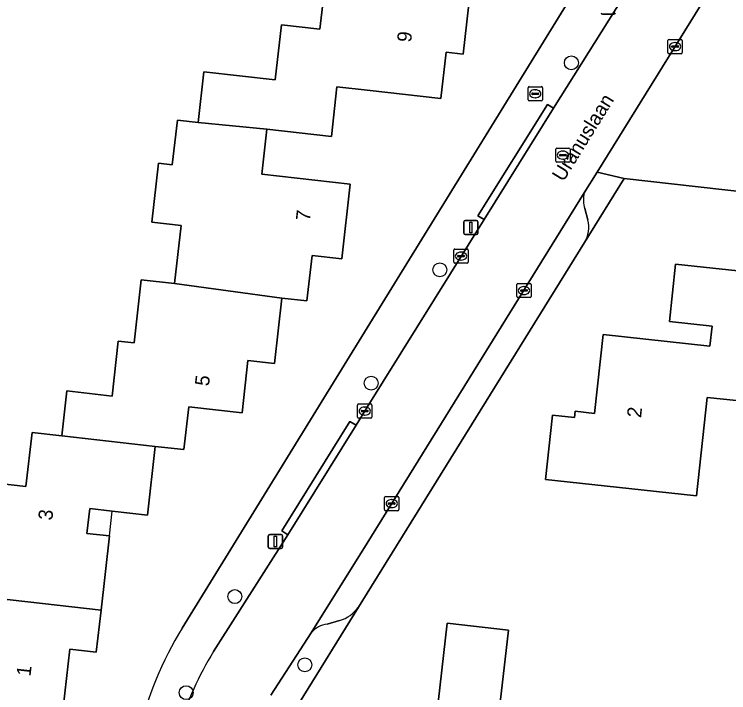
# Model space of a CAD drawing. Extents: x 162396 to 163643, y 386452 to 387406.
# Drawn here: x 162975.2 to 163025.4, y 386589 to 386636.7 of the extents above; entities that cross this region are included whole.
import ezdxf

# ---------------------------------------------------------------- set-up
doc = ezdxf.new("R2010")
doc.units = 0
for name, color, linetype in [('IMGEO_Boom', 7, 'Continuous'), ('IMGEO_Brandkraan', 7, 'Continuous'), ('IMGEO_Erf', 7, 'Continuous'), ('IMGEO_Kolk', 7, 'Continuous'), ('IMGEO_Lichtmast', 7, 'Continuous'), ('IMGEO_Openbare_ruimte_label', 7, 'Continuous'), ('IMGEO_Pand', 7, 'Continuous'), ('IMGEO_Pand_nummerreeks', 7, 'Continuous'), ('IMGEO_Pand_overbouw', 7, 'Continuous'), ('IMGEO_Parkeervlak_open', 7, 'Continuous'), ('IMGEO_Rijbaan_lokaal_open', 7, 'Continuous'), ('IMGEO_Rioolput', 7, 'Continuous'), ('IMGEO_Voetpad_open', 7, 'Continuous')]:
    doc.layers.add(name, color=color, linetype=linetype)

msp = doc.modelspace()

# ---------------------------------------------------------------- linework, layer by layer
at = {"layer": 'IMGEO_Boom'}
for centre in [(163014.332, 386633.247), (163005.108, 386618.72), (163000.288, 386610.754), (162990.719, 386595.774), (162995.628, 386590.981), (162987.307, 386589.03)]:
    msp.add_circle(centre, 0.489, dxfattribs=at)
at = {"layer": 'IMGEO_Brandkraan'}
for p, q in [((163011.297, 386630.65), (163011.297, 386631.502)), ((163011.372, 386631.576), (163012.224, 386631.576)), ((163011.599, 386631.119), (163011.997, 386631.119)), ((163011.785, 386631.356), (163011.81, 386631.356)), ((163012.298, 386631.502), (163012.298, 386630.65)), ((163011.556, 386631.07), (163011.556, 386631.082)), ((163011.994, 386631.033), (163011.596, 386631.033)), ((163011.808, 386630.796), (163011.783, 386630.796)), ((163012.04, 386631.082), (163012.04, 386631.07)), ((163012.224, 386630.576), (163011.372, 386630.576))]:
    msp.add_line(p, q, dxfattribs=at)
for points in [[(163011.297, 386630.65), (163011.297, 386631.502)], [(163011.372, 386631.576), (163012.224, 386631.576)], [(163012.298, 386631.502), (163012.298, 386630.65)], [(163012.224, 386630.576), (163011.372, 386630.576)]]:
    msp.add_lwpolyline(points, dxfattribs=at)
for centre, radius, start, end in [((163011.374, 386631.5), 0.0765, 91.552, 178.448), ((163011.374, 386631.5), 0.0765, 91.552, 178.448), ((163011.596, 386631.079), 0.0403, 85.8775, 175.7526), ((163012.001, 386631.081), 0.0386, 1.7309, 96.639), ((163012.222, 386631.5), 0.0765, 1.552, 88.448), ((163012.222, 386631.5), 0.0765, 1.552, 88.448), ((163011.374, 386630.652), 0.0765, 181.552, 268.448), ((163011.374, 386630.652), 0.0765, 181.552, 268.448), ((163011.593, 386631.069), 0.0366, 178.938, 274.7102), ((163011.997, 386631.076), 0.043, 264.8664, 352.4533), ((163012.222, 386630.652), 0.0765, 271.552, 358.448), ((163012.222, 386630.652), 0.0765, 271.552, 358.448)]:
    msp.add_arc(centre, radius, start, end, dxfattribs=at)
for centre, major_axis, ratio, start_param, end_param in [((163011.784, 386631.076), (-0.387, 0.002), 0.722429, 4.712389, 7.853982), ((163011.809, 386631.076), (-0.39, 0.002), 0.717154, 1.570796, 4.712389)]:
    msp.add_ellipse(centre, major_axis=major_axis, ratio=ratio, start_param=start_param, end_param=end_param, dxfattribs=at)
at = {"layer": 'IMGEO_Erf'}
for points in [[(163000, 386614.638), (163016.213, 386640.977)], [(162971.713, 386604.006), (162976.062, 386603.513), (162976.49, 386607.292), (162978.575, 386607.056), (162978.932, 386610.213), (162982.104, 386609.853), (162982.541, 386613.71), (162983.653, 386613.584), (162984.156, 386618.023), (162986.481, 386617.76), (162986.942, 386621.82), (162984.888, 386622.053), (162985.358, 386626.198), (162986.33, 386626.088), (162986.685, 386629.222), (162988.151, 386629.056), (162988.554, 386632.618), (162993.56, 386632.05), (162993.998, 386635.917), (162996.689, 386635.612), (162997.141, 386639.603)], [(163007.248, 386638.423), (163006.731, 386633.862), (163005.545, 386633.996), (163005.176, 386630.736), (163000, 386631.322), (162997.885, 386631.562), (162997.491, 386628.087), (162992.971, 386628.599), (162992.606, 386625.428), (162998.818, 386624.724), (162998.224, 386619.481), (162996.135, 386619.718), (162995.774, 386616.533), (162994.015, 386616.732), (162993.493, 386612.131), (162991.642, 386612.341), (162991.228, 386608.683), (162987.489, 386609.107), (162987.147, 386606.091), (162985.137, 386606.319), (162984.591, 386601.496), (162982.119, 386601.776), (162980.538, 386601.955), (162980.341, 386600.214), (162981.921, 386600.035), (162981.331, 386594.829), (162980.996, 386591.874), (162979.134, 386592.085), (162978.667, 386587.962)], [(163085.957, 386598.897), (163082.131, 386599.35), (163084.149, 386617.704), (163047.319, 386621.839), (163018.036, 386625.127), (163015.257, 386620.642), (163000, 386596.016), (162999.395, 386595.039), (162995.246, 386588.336)], [(162987.029, 386593.566), (163000, 386614.638)]]:
    msp.add_lwpolyline(points, dxfattribs=at)
for points in [[(163026.695, 386608.155), (163026.833, 386609.438), (163023.863, 386609.759), (163023.116, 386602.852), (163017.494, 386603.46), (163012.522, 386603.997), (163013.01, 386608.517), (163014.544, 386608.351), (163014.591, 386608.783), (163015.958, 386608.635), (163016.556, 386614.165), (163024.05, 386613.355), (163024.202, 386614.764), (163021.21, 386615.088), (163021.646, 386619.122), (163027.975, 386618.438), (163031.846, 386618.019), (163032.005, 386619.49), (163039.963, 386618.63), (163039.426, 386613.659), (163038.838, 386608.225), (163030.817, 386609.092), (163030.669, 386607.725)], [(163009.917, 386593.413), (163008.329, 386579.606), (163005.77, 386579.901), (163004.964, 386572.892), (163001.314, 386573.311), (163001.266, 386572.892), (163000, 386573.038), (162998.149, 386573.251), (162998.203, 386573.725), (162997.532, 386573.802), (162998.668, 386583.682), (162999.078, 386587.246), (163003.047, 386586.79), (163003.13, 386587.513), (163004.87, 386587.313), (163005.628, 386593.906)]]:
    msp.add_lwpolyline(points, close=True, dxfattribs=at)
msp.add_arc((163008.512, 386580.334), 25.231, 148.3699, 185.0018, dxfattribs=at)
at = {"layer": 'IMGEO_Kolk'}
for p, q in [((163021.109, 386633.964), (163021.109, 386634.816)), ((163021.184, 386634.89), (163022.036, 386634.89)), ((163021.597, 386634.67), (163021.622, 386634.67)), ((163022.11, 386634.816), (163022.11, 386633.964)), ((163021.368, 386634.384), (163021.368, 386634.396)), ((163021.806, 386634.347), (163021.408, 386634.347)), ((163021.411, 386634.433), (163021.809, 386634.433)), ((163021.62, 386634.11), (163021.595, 386634.11)), ((163021.852, 386634.396), (163021.852, 386634.384)), ((163022.036, 386633.89), (163021.184, 386633.89)), ((163006.09, 386619.252), (163006.09, 386620.104)), ((163006.165, 386620.178), (163007.017, 386620.178)), ((163007.091, 386620.104), (163007.091, 386619.252)), ((163006.349, 386619.672), (163006.349, 386619.684)), ((163006.787, 386619.635), (163006.389, 386619.635)), ((163006.392, 386619.721), (163006.79, 386619.721)), ((163006.578, 386619.958), (163006.603, 386619.958)), ((163006.833, 386619.684), (163006.833, 386619.672)), ((163007.017, 386619.178), (163006.165, 386619.178)), ((163006.601, 386619.398), (163006.576, 386619.398)), ((163010.506, 386616.838), (163010.506, 386617.69)), ((163010.581, 386617.764), (163011.433, 386617.764)), ((163011.507, 386617.69), (163011.507, 386616.838)), ((163010.765, 386617.258), (163010.765, 386617.27)), ((163011.203, 386617.221), (163010.805, 386617.221)), ((163010.808, 386617.307), (163011.206, 386617.307)), ((163010.994, 386617.544), (163011.019, 386617.544)), ((163011.249, 386617.27), (163011.249, 386617.258)), ((163011.433, 386616.764), (163010.581, 386616.764)), ((163011.017, 386616.984), (163010.992, 386616.984)), ((162999.335, 386608.372), (162999.335, 386609.224)), ((162999.41, 386609.298), (163000.262, 386609.298)), ((162999.823, 386609.078), (162999.848, 386609.078)), ((163000.336, 386609.224), (163000.336, 386608.372)), ((162999.594, 386608.792), (162999.594, 386608.804)), ((163000.032, 386608.755), (162999.634, 386608.755)), ((162999.637, 386608.841), (163000.035, 386608.841)), ((163000.078, 386608.804), (163000.078, 386608.792)), ((163000.262, 386608.298), (162999.41, 386608.298)), ((162999.846, 386608.518), (162999.821, 386608.518)), ((163001.226, 386601.881), (163001.226, 386602.733)), ((163001.301, 386602.807), (163002.153, 386602.807)), ((163001.714, 386602.587), (163001.739, 386602.587)), ((163002.227, 386602.733), (163002.227, 386601.881)), ((163001.485, 386602.301), (163001.485, 386602.313)), ((163001.923, 386602.264), (163001.525, 386602.264)), ((163001.528, 386602.35), (163001.926, 386602.35)), ((163001.737, 386602.027), (163001.712, 386602.027)), ((163001.969, 386602.313), (163001.969, 386602.301)), ((163002.153, 386601.807), (163001.301, 386601.807))]:
    msp.add_line(p, q, dxfattribs=at)
for points in [[(163021.109, 386633.964), (163021.109, 386634.816)], [(163021.184, 386634.89), (163022.036, 386634.89)], [(163022.11, 386634.816), (163022.11, 386633.964)], [(163022.036, 386633.89), (163021.184, 386633.89)], [(163006.09, 386619.252), (163006.09, 386620.104)], [(163006.165, 386620.178), (163007.017, 386620.178)], [(163007.091, 386620.104), (163007.091, 386619.252)], [(163007.017, 386619.178), (163006.165, 386619.178)], [(163010.506, 386616.838), (163010.506, 386617.69)], [(163010.581, 386617.764), (163011.433, 386617.764)], [(163011.507, 386617.69), (163011.507, 386616.838)], [(163011.433, 386616.764), (163010.581, 386616.764)], [(162999.335, 386608.372), (162999.335, 386609.224)], [(162999.41, 386609.298), (163000.262, 386609.298)], [(163000.336, 386609.224), (163000.336, 386608.372)], [(163000.262, 386608.298), (162999.41, 386608.298)], [(163001.226, 386601.881), (163001.226, 386602.733)], [(163001.301, 386602.807), (163002.153, 386602.807)], [(163002.227, 386602.733), (163002.227, 386601.881)], [(163002.153, 386601.807), (163001.301, 386601.807)]]:
    msp.add_lwpolyline(points, dxfattribs=at)
for centre, radius, start, end in [((163021.186, 386634.814), 0.0765, 91.552, 178.448), ((163021.186, 386634.814), 0.0765, 91.552, 178.448), ((163022.034, 386634.814), 0.0765, 1.552, 88.448), ((163022.034, 386634.814), 0.0765, 1.552, 88.448), ((163021.408, 386634.393), 0.0403, 85.8775, 175.7526), ((163021.405, 386634.383), 0.0366, 178.938, 274.7102), ((163021.809, 386634.39), 0.043, 264.8664, 352.4533), ((163021.813, 386634.395), 0.0386, 1.7309, 96.639), ((163021.186, 386633.966), 0.0765, 181.552, 268.448), ((163021.186, 386633.966), 0.0765, 181.552, 268.448), ((163022.034, 386633.966), 0.0765, 271.552, 358.448), ((163022.034, 386633.966), 0.0765, 271.552, 358.448), ((163006.167, 386620.102), 0.0765, 91.552, 178.448), ((163006.167, 386620.102), 0.0765, 91.552, 178.448), ((163007.015, 386620.102), 0.0765, 1.552, 88.448), ((163007.015, 386620.102), 0.0765, 1.552, 88.448), ((163006.389, 386619.681), 0.0403, 85.8775, 175.7526), ((163006.386, 386619.671), 0.0366, 178.938, 274.7102), ((163006.79, 386619.678), 0.043, 264.8664, 352.4533), ((163006.794, 386619.683), 0.0386, 1.7309, 96.639), ((163006.167, 386619.254), 0.0765, 181.552, 268.448), ((163006.167, 386619.254), 0.0765, 181.552, 268.448), ((163007.015, 386619.254), 0.0765, 271.552, 358.448), ((163007.015, 386619.254), 0.0765, 271.552, 358.448), ((163010.583, 386617.688), 0.0765, 91.552, 178.448), ((163010.583, 386617.688), 0.0765, 91.552, 178.448), ((163011.431, 386617.688), 0.0765, 1.552, 88.448), ((163011.431, 386617.688), 0.0765, 1.552, 88.448), ((163010.805, 386617.267), 0.0403, 85.8775, 175.7526), ((163010.802, 386617.257), 0.0366, 178.938, 274.7102), ((163011.206, 386617.264), 0.043, 264.8664, 352.4533), ((163011.21, 386617.269), 0.0386, 1.7309, 96.639), ((163010.583, 386616.84), 0.0765, 181.552, 268.448), ((163010.583, 386616.84), 0.0765, 181.552, 268.448), ((163011.431, 386616.84), 0.0765, 271.552, 358.448), ((163011.431, 386616.84), 0.0765, 271.552, 358.448), ((162999.412, 386609.222), 0.0765, 91.552, 178.448), ((162999.412, 386609.222), 0.0765, 91.552, 178.448), ((163000.26, 386609.222), 0.0765, 1.552, 88.448), ((163000.26, 386609.222), 0.0765, 1.552, 88.448), ((162999.634, 386608.801), 0.0403, 85.8775, 175.7526), ((162999.631, 386608.791), 0.0366, 178.938, 274.7102), ((163000.035, 386608.798), 0.043, 264.8664, 352.4533), ((163000.039, 386608.803), 0.0386, 1.7309, 96.639), ((162999.412, 386608.374), 0.0765, 181.552, 268.448), ((162999.412, 386608.374), 0.0765, 181.552, 268.448), ((163000.26, 386608.374), 0.0765, 271.552, 358.448), ((163000.26, 386608.374), 0.0765, 271.552, 358.448), ((163001.303, 386602.731), 0.0765, 91.552, 178.448), ((163001.303, 386602.731), 0.0765, 91.552, 178.448), ((163002.151, 386602.731), 0.0765, 1.552, 88.448), ((163002.151, 386602.731), 0.0765, 1.552, 88.448), ((163001.525, 386602.31), 0.0403, 85.8775, 175.7526), ((163001.522, 386602.3), 0.0366, 178.938, 274.7102), ((163001.926, 386602.307), 0.043, 264.8664, 352.4533), ((163001.93, 386602.312), 0.0386, 1.7309, 96.639), ((163001.303, 386601.883), 0.0765, 181.552, 268.448), ((163001.303, 386601.883), 0.0765, 181.552, 268.448), ((163002.151, 386601.883), 0.0765, 271.552, 358.448), ((163002.151, 386601.883), 0.0765, 271.552, 358.448)]:
    msp.add_arc(centre, radius, start, end, dxfattribs=at)
for centre, major_axis, ratio, start_param, end_param in [((163021.596, 386634.39), (-0.387, 0.002), 0.722429, 4.712389, 7.853982), ((163021.621, 386634.39), (-0.39, 0.002), 0.717154, 1.570796, 4.712389), ((163006.577, 386619.678), (-0.387, 0.002), 0.722429, 4.712389, 7.853982), ((163006.602, 386619.678), (-0.39, 0.002), 0.717154, 1.570796, 4.712389), ((163010.993, 386617.264), (-0.387, 0.002), 0.722429, 4.712389, 7.853982), ((163011.018, 386617.264), (-0.39, 0.002), 0.717154, 1.570796, 4.712389), ((162999.822, 386608.798), (-0.387, 0.002), 0.722429, 4.712389, 7.853982), ((162999.847, 386608.798), (-0.39, 0.002), 0.717154, 1.570796, 4.712389), ((163001.713, 386602.307), (-0.387, 0.002), 0.722429, 4.712389, 7.853982), ((163001.738, 386602.307), (-0.39, 0.002), 0.717154, 1.570796, 4.712389)]:
    msp.add_ellipse(centre, major_axis=major_axis, ratio=ratio, start_param=start_param, end_param=end_param, dxfattribs=at)
at = {"layer": 'IMGEO_Lichtmast'}
for p, q in [((163017.318, 386636.658), (163016.528, 386636.658)), ((163016.528, 386636.658), (163017.318, 386636.658)), ((163006.784, 386621.291), (163006.784, 386622.091)), ((163006.784, 386622.091), (163006.784, 386621.291)), ((163006.884, 386622.191), (163007.674, 386622.191)), ((163007.674, 386622.191), (163006.884, 386622.191)), ((163007.774, 386622.091), (163007.774, 386621.291)), ((163007.774, 386621.291), (163007.774, 386622.091)), ((163007.674, 386621.191), (163006.884, 386621.191)), ((163006.884, 386621.191), (163007.674, 386621.191)), ((162993.069, 386599.246), (162993.069, 386600.046)), ((162993.069, 386600.046), (162993.069, 386599.246)), ((162993.169, 386600.146), (162993.959, 386600.146)), ((162993.959, 386600.146), (162993.169, 386600.146)), ((162994.059, 386600.046), (162994.059, 386599.246)), ((162994.059, 386599.246), (162994.059, 386600.046)), ((162993.959, 386599.146), (162993.169, 386599.146)), ((162993.169, 386599.146), (162993.959, 386599.146))]:
    msp.add_line(p, q, dxfattribs=at)
for points in [[(163007.204, 386622.066), (163007.354, 386622.066), (163007.354, 386621.316), (163007.204, 386621.316), (163007.204, 386622.066)], [(162993.489, 386600.021), (162993.639, 386600.021), (162993.639, 386599.271), (162993.489, 386599.271), (162993.489, 386600.021)]]:
    msp.add_lwpolyline(points, dxfattribs=at)
for centre, start, end in [((163016.528, 386636.758), 180, 270), ((163016.528, 386636.758), 180, 270), ((163017.318, 386636.758), 270, 0), ((163017.318, 386636.758), 270, 0), ((163006.884, 386622.091), 90, 180), ((163006.884, 386622.091), 90, 180), ((163007.674, 386622.091), 0, 90), ((163007.674, 386622.091), 360, 90), ((163006.884, 386621.291), 180, 270), ((163006.884, 386621.291), 180, 270), ((163007.674, 386621.291), 270, 0), ((163007.674, 386621.291), 270, 0), ((162993.169, 386600.046), 90, 180), ((162993.169, 386600.046), 90, 180), ((162993.959, 386600.046), 0, 90), ((162993.959, 386600.046), 360, 90), ((162993.169, 386599.246), 180, 270), ((162993.169, 386599.246), 180, 270), ((162993.959, 386599.246), 270, 0), ((162993.959, 386599.246), 270, 0)]:
    msp.add_arc(centre, 0.1, start, end, dxfattribs=at)
at = {"layer": 'IMGEO_Pand'}
for points in [[(163000, 386639.272), (162997.929, 386639.514), (162997.141, 386639.603), (162996.689, 386635.612), (162993.998, 386635.917), (162993.56, 386632.05), (162988.554, 386632.618), (162988.151, 386629.056), (162992.971, 386628.599), (162997.491, 386628.087), (162997.885, 386631.562), (163000, 386631.322), (163005.176, 386630.736), (163005.545, 386633.996), (163006.731, 386633.862), (163007.248, 386638.423)], [(162988.151, 386629.056), (162986.685, 386629.222), (162986.33, 386626.088), (162985.358, 386626.198), (162984.888, 386622.053), (162986.942, 386621.82), (162986.481, 386617.76), (162994.015, 386616.732), (162995.774, 386616.533), (162996.135, 386619.718), (162998.224, 386619.481), (162998.818, 386624.724), (162992.606, 386625.428), (162992.971, 386628.599)], [(163027.975, 386618.438), (163021.646, 386619.122), (163021.21, 386615.088), (163024.202, 386614.764), (163024.05, 386613.355), (163016.556, 386614.165), (163015.958, 386608.635), (163014.591, 386608.783), (163014.544, 386608.351), (163013.01, 386608.517), (163012.522, 386603.997), (163017.494, 386603.46), (163023.116, 386602.852), (163023.863, 386609.759), (163026.833, 386609.438), (163027.01, 386611.079)], [(162985.137, 386606.319), (162987.147, 386606.091), (162987.489, 386609.107), (162991.228, 386608.683), (162991.642, 386612.341), (162993.493, 386612.131), (162994.015, 386616.732), (162986.481, 386617.76), (162984.156, 386618.023), (162983.653, 386613.584), (162982.541, 386613.71), (162982.104, 386609.853), (162978.932, 386610.213), (162978.575, 386607.056)], [(162980.538, 386601.955), (162982.119, 386601.776), (162984.591, 386601.496), (162985.137, 386606.319), (162978.575, 386607.056), (162976.49, 386607.292), (162976.062, 386603.513), (162971.713, 386604.006), (162970.913, 386596.952), (162970.846, 386596.36), (162970.808, 386596.022), (162981.331, 386594.829), (162981.921, 386600.035), (162980.341, 386600.214)], [(162979.134, 386592.085), (162980.996, 386591.874), (162981.331, 386594.829), (162970.808, 386596.022), (162969.798, 386596.136), (162969.315, 386591.875), (162966.289, 386592.218), (162965.516, 386585.402), (162968.957, 386585.013), (162974.641, 386584.395), (162975.09, 386588.368), (162978.667, 386587.962)], [(163009.917, 386593.413), (163005.628, 386593.906), (163004.87, 386587.313), (163003.13, 386587.513), (163003.047, 386586.79), (162999.078, 386587.246), (162998.668, 386583.682), (162997.532, 386573.802), (162998.203, 386573.725), (162998.149, 386573.251), (163000, 386573.038), (163001.266, 386572.892), (163001.314, 386573.311), (163004.964, 386572.892), (163005.77, 386579.901), (163008.329, 386579.606)]]:
    msp.add_lwpolyline(points, close=True, dxfattribs=at)
at = {"layer": 'IMGEO_Pand_overbouw'}
msp.add_lwpolyline([(162982.119, 386601.776), (162980.538, 386601.955), (162980.341, 386600.214), (162981.921, 386600.035)], close=True, dxfattribs=at)
at = {"layer": 'IMGEO_Parkeervlak_open'}
for points in [[(163023.43, 386637.336), (163016.146, 386625.58), (163018.036, 386625.127), (163047.319, 386621.839), (163047.656, 386624.851), (163049.253, 386639.503)], [(163015.235, 386624.111), (163000, 386599.532), (162996.086, 386593.237)], [(163015.492, 386622.219), (163015.278, 386623.015)], [(162999.395, 386595.039), (163000, 386596.016), (163015.257, 386620.642)], [(162997.198, 386593.838), (162998.074, 386594.092)]]:
    msp.add_lwpolyline(points, dxfattribs=at)
for centre, radius, start, end in [((163017.207, 386623.64), 2.028, 166.5575, 197.936), ((163013.505, 386621.709), 2.052, 328.6585, 14.3901), ((162997.321, 386596.537), 2.558, 287.1129, 324.1592), ((162997.385, 386592.163), 1.685, 96.3587, 140.4209)]:
    msp.add_arc(centre, radius, start, end, dxfattribs=at)
at = {"layer": 'IMGEO_Rijbaan_lokaal_open'}
for points in [[(163018.389, 386638.527), (163013.077, 386630.067), (163008.205, 386622.242), (163000, 386609.064), (162999.223, 386607.813), (162994.449, 386600.121), (162989.231, 386591.917)], [(162993.242, 386588.843), (162996.086, 386593.237), (163000, 386599.532), (163015.235, 386624.111), (163016.146, 386625.58), (163023.43, 386637.336)]]:
    msp.add_lwpolyline(points, dxfattribs=at)
msp.add_arc((163009.002, 386579.745), 23.218, 148.3818, 163.0597, dxfattribs=at)
at = {"layer": 'IMGEO_Rioolput'}
for p, q in [((163013.237, 386626.342), (163013.237, 386627.194)), ((163013.312, 386627.268), (163014.164, 386627.268)), ((163014.238, 386627.194), (163014.238, 386626.342)), ((163013.496, 386626.762), (163013.496, 386626.774)), ((163013.934, 386626.725), (163013.536, 386626.725)), ((163013.539, 386626.811), (163013.937, 386626.811)), ((163013.725, 386627.048), (163013.75, 386627.048)), ((163013.98, 386626.774), (163013.98, 386626.762)), ((163014.164, 386626.268), (163013.312, 386626.268)), ((163013.748, 386626.488), (163013.723, 386626.488))]:
    msp.add_line(p, q, dxfattribs=at)
for points in [[(163013.237, 386626.342), (163013.237, 386627.194)], [(163013.312, 386627.268), (163014.164, 386627.268)], [(163014.238, 386627.194), (163014.238, 386626.342)], [(163014.164, 386626.268), (163013.312, 386626.268)]]:
    msp.add_lwpolyline(points, dxfattribs=at)
for centre, radius, start, end in [((163013.314, 386627.192), 0.0765, 91.552, 178.448), ((163013.314, 386627.192), 0.0765, 91.552, 178.448), ((163014.162, 386627.192), 0.0765, 1.552, 88.448), ((163014.162, 386627.192), 0.0765, 1.552, 88.448), ((163013.536, 386626.771), 0.0403, 85.8775, 175.7526), ((163013.533, 386626.761), 0.0366, 178.938, 274.7102), ((163013.937, 386626.768), 0.043, 264.8664, 352.4533), ((163013.941, 386626.773), 0.0386, 1.7309, 96.639), ((163013.314, 386626.344), 0.0765, 181.552, 268.448), ((163013.314, 386626.344), 0.0765, 181.552, 268.448), ((163014.162, 386626.344), 0.0765, 271.552, 358.448), ((163014.162, 386626.344), 0.0765, 271.552, 358.448)]:
    msp.add_arc(centre, radius, start, end, dxfattribs=at)
for centre, major_axis, ratio, start_param, end_param in [((163013.724, 386626.768), (-0.387, 0.002), 0.722429, 4.712389, 7.853982), ((163013.749, 386626.768), (-0.39, 0.002), 0.717154, 1.570796, 4.712389)]:
    msp.add_ellipse(centre, major_axis=major_axis, ratio=ratio, start_param=start_param, end_param=end_param, dxfattribs=at)
at = {"layer": 'IMGEO_Voetpad_open'}
for points in [[(163016.213, 386640.977), (163000, 386614.638), (162987.029, 386593.566)], [(162989.231, 386591.917), (162994.449, 386600.121), (162994.025, 386600.384), (162998.799, 386608.076), (162999.223, 386607.813), (163000, 386609.064), (163008.205, 386622.242), (163007.771, 386622.512), (163012.648, 386630.334), (163013.077, 386630.067), (163018.389, 386638.527)], [(163018.036, 386625.127), (163016.146, 386625.58), (163015.235, 386624.111)], [(163015.257, 386620.642), (163018.036, 386625.127)], [(163015.278, 386623.015), (163015.492, 386622.219)], [(162995.246, 386588.336), (162999.395, 386595.039)], [(162998.074, 386594.092), (162997.198, 386593.838)], [(162996.086, 386593.237), (162993.242, 386588.843)]]:
    msp.add_lwpolyline(points, dxfattribs=at)
for points in [[(163013.077, 386630.067), (163012.648, 386630.334), (163007.771, 386622.512), (163008.205, 386622.242)], [(162999.223, 386607.813), (162998.799, 386608.076), (162994.025, 386600.384), (162994.449, 386600.121)]]:
    msp.add_lwpolyline(points, close=True, dxfattribs=at)
for centre, radius, start, end in [((163017.207, 386623.64), 2.028, 166.5575, 197.936), ((163013.505, 386621.709), 2.052, 328.6585, 14.3901), ((162997.321, 386596.537), 2.558, 287.1129, 324.1592), ((163008.512, 386580.334), 25.231, 148.3699, 185.0018), ((162997.385, 386592.163), 1.685, 96.3587, 140.4209), ((163009.002, 386579.745), 23.218, 148.3818, 163.0597)]:
    msp.add_arc(centre, radius, start, end, dxfattribs=at)

# ---------------------------------------------------------------- texts
at = {"layer": 'IMGEO_Openbare_ruimte_label'}
msp.add_text('Uranuslaan', height=1, rotation=58.2498, dxfattribs=at).set_placement((163013.765, 386624.85))
at = {"layer": 'IMGEO_Pand_nummerreeks'}
for s, rotation, p in [('9', 83.5422, (163003.084, 386634.658)), ('7', 83.5363, (162995.986, 386622.112)), ('5', 83.5429, (162988.9, 386610.521)), ('2', 83.8282, (163019.22, 386608.296)), ('3', 83.543, (162977.905, 386601.095)), ('1', 83.5372, (162976.379, 386590.148))]:
    msp.add_text(s, height=1, rotation=rotation, dxfattribs=at).set_placement(p)

doc.saveas('drawing.dxf')
